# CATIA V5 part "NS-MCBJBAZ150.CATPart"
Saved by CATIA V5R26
Part number: NS-MCBJBAZ150
Bounding box of the stored display mesh (mm): x -60 to 120, y 0 to 198, z -110.177 to 60
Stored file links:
  R:\Document\坂尻\その他\ナベヤデータ変換\安全カバーキャスター\MCBJSZAZ150\NS-MCBJBAZ150.CATPart
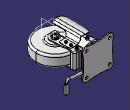
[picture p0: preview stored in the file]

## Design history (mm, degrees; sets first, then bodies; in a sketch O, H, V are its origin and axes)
Body1 (main body)
  Solid1: solid without history
  Body2
    Solid2: solid without history
  Assemble1: tool Body2
  Body3
    Solid3: solid without history
  Assemble2: tool Body3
